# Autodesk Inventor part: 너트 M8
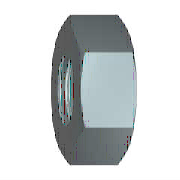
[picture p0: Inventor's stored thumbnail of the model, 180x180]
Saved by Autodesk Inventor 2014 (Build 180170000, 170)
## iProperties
IsCustomPart: 1
Created: 2012-02
Part Number: 너트 M8
Material: 강철, 연강
Description: 6각 너트 및 6각 가는 너트
Document SubType Name: Modeling
Standard: KS B 1012
Designer: mduedu
Standards Organization: KS
Language: ko-KR
Size Designation: M 8
Categories: <MemberInstance><Categories><Category DisplayName="조임쇠" InternalName="e4da775c-781d-43d5-af7c-5136215cf5a6" Mnemonic="FSTN"><Category DisplayName="너트" InternalN
Density: 1 g/cm^3
Appearance: Steel
Author: mduedu
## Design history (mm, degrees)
sketch "스케치1"
  geometry: L1 (-7.506, 0)-(-3.753, 6.5); L2 (-3.753, 6.5)-(3.753, 6.5); L3 (3.753, 6.5)-(7.506, 0); L4 (7.506, 0)-(3.753, -6.5); L5 (3.753, -6.5)-(-3.753, -6.5); L6 (-3.753, -6.5)-(-7.506, 0); 2 further points
  constraints: 12 end point, 1 coincident, 1 horizontal, 11 other
  dimensions: "d0" = 15.01111 distance of L3.end L1.start (= 1.1547 x SW)
extrude "본체" new body sketch "스케치1" distance "d1" = 5 (= KOH); taper "d2" = 0 deg
sketch "스케치2"
  geometry: L1 (0, 3.753)-(0, 7.506) reference; L2 (0, 7.506)-(5, 7.506) reference; L3 (5, 3.753)-(5, 7.506) reference; L4 (-1, 0)-(6, 0) reference; L5 (0.581, 7.506)-(0, 6.5); L6 (4.419, 7.506)-(5, 6.5)
  constraints: 4 end point, 4 point on line
  dimensions: "d3" = 30 deg angle of L1 L5 (= ANG1); "d4" = 30 deg angle of L3 L6 (= ANG2); "d5" = 13 diameter of L5.end L4 (= SW0); "d6" = 13 diameter of L6.end L4 (= SW01)
revolve "모따기1" sketch "스케치2" stored, may be unused: angle "d7" = 90 deg
sketch "스케치3"
  geometry: A1 r 6.5 centre (0, 0) between (-3.25, -5.629) and (3.25, -5.629) reference; 1 further point
  constraints: 1 coincident
hole "스레드" sketch "스케치3" at (0, 0) diameter "d25" = 6.647; stored, may be unused: countersink angle "d29" = 82 deg, drill point angle "d31" = 118 deg; dims "d26" = 6, "d27" = 4, "d28" = 2, "d30" = 8
workaxis "Work Axis1"
workplane "Work Plane1"
body "Solid1"
chamfer "모따기2" distance "d8" = 0.67658 (= -0.5 x GD1 + 0.5 x NND); stored, may be unused: angle "d9" = 30 deg, second distance "d40" = 0.67658 (= -0.5 x GD1 + 0.5 x NND)
chamfer "모따기3" distance "d10" = 0.67658 (= -0.5 x GD1 + 0.5 x NND); stored, may be unused: angle "d11" = 30 deg, second distance "d41" = 0.67658 (= -0.5 x GD1 + 0.5 x NND)
other parameters: "ANG1" = 30 deg [user parameter; used in 1 equation term], "ANG2" = 30 deg [user parameter; used in 1 equation term], "NND" = 8 [user parameter; used in 4 equation terms], "KOH" = 5 [user parameter; used in 1 equation term], "SW" = 13 [user parameter; used in 4 equation terms], "SW0" = 13 (= SW) [user parameter; used in 1 equation term], "SW01" = 13 (= SW) [user parameter; used in 1 equation term], "GD1" = 6.64684 (computed from THREADDIA, PTC, TOA) [user parameter; used in 4 equation terms], "d13" = 0, "d14" = 0, "d39" = 0, "d42" = 0, "GUL" = 0.67658 (= 0.541266 x PTC) [user parameter], "TPU" = 8 (computed from PTC) [user parameter], "THREADDIA" = 8 [user parameter; used in 1 equation term], "TOA" = 30 deg [user parameter; used in 1 equation term], "PTC" = 1.25 [user parameter; used in 4 equation terms], "E0" = 15.015 (= 1.155 x SW) [user parameter], "GAL" = 0.67658 (= 0.541266 x PTC) [user parameter]
